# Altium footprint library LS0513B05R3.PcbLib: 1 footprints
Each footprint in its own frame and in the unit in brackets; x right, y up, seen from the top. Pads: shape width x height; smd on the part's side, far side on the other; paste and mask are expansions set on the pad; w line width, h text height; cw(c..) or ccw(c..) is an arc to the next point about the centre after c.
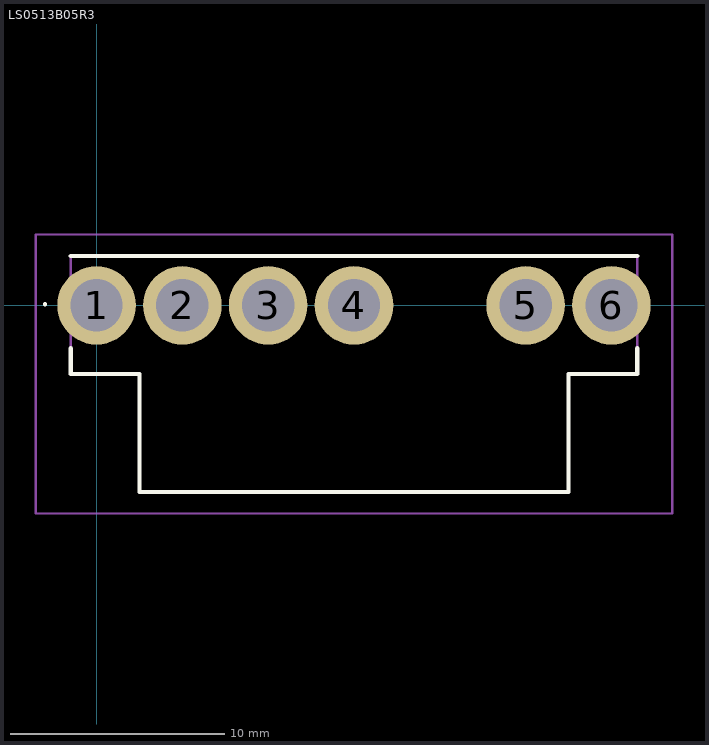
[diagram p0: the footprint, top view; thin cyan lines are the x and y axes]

## LS0513B05R3 [mm]
pads (6):
  round 3.66 hole 2.44: 1(0,0) 2(4,0) 3(8,0) 4(12,0) 5(20,0) 6(24,0)
Top Overlay:
  lines w0.1: -2.4,0 -2.4,0 ; -2.4,0 ccw(c-2.4,0.05) -2.4,0.1 ; -2.4,0 cw(c-2.4,0.05) -2.4,0.1 ; -2.4,0.1 -2.4,0.1
  lines w0.2: -1.2,-2 -1.2,-3.2 2,-3.2 2,-8.7 22,-8.7 22,-3.2 25.2,-3.2 25.2,-2 ; -1.2,2.3 25.2,2.3
Mechanical 15:
  lines w0.1: -1.2,-3.2 -1.2,2.3 25.2,2.3 25.2,-3.2 22,-3.2 22,-8.7 2,-8.7 2,-3.2 -1.2,-3.2
Mechanical 20:
  lines w0.1: -2.83,-9.7 26.83,-9.7 26.83,3.3 -2.83,3.3 -2.83,-9.7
